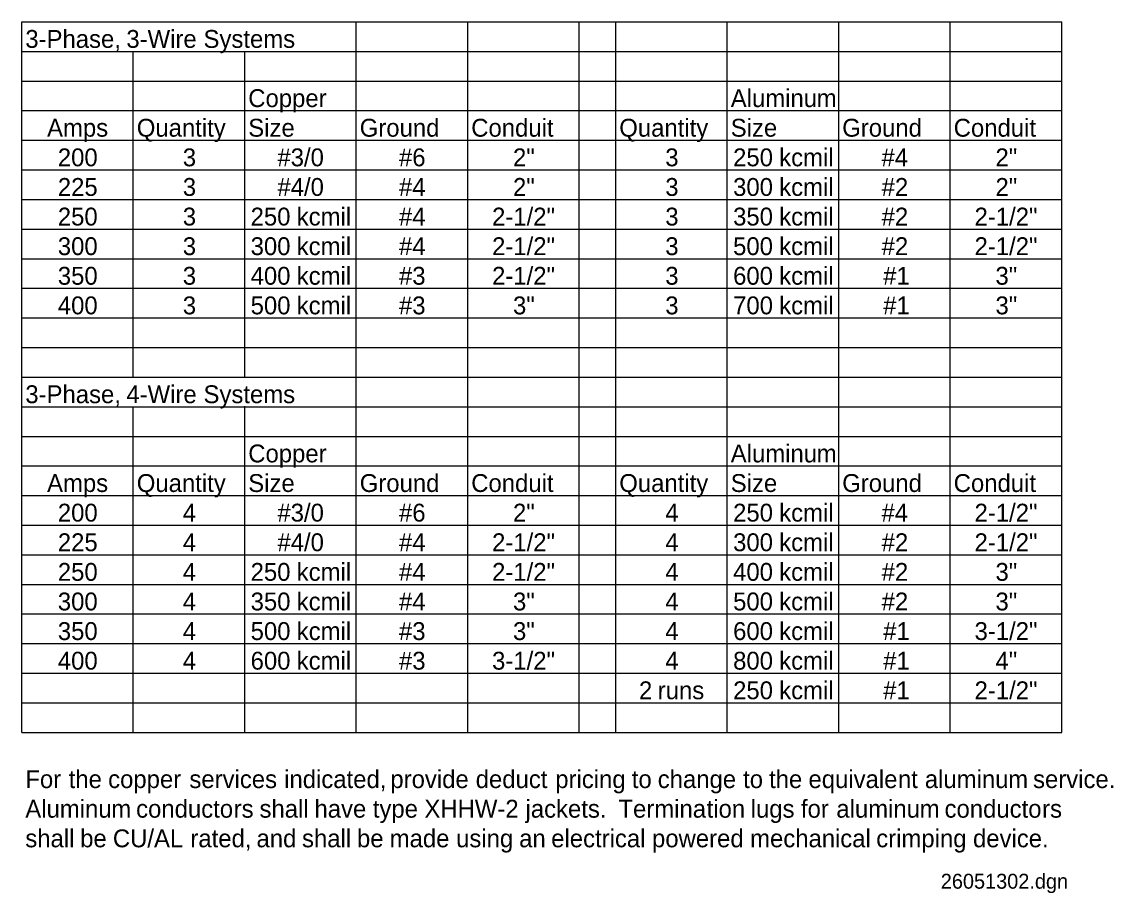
# Model space of a CAD drawing. Extents: x 10073 to 10121.9, y 10117.2 to 10156.2.
import ezdxf

# ---------------------------------------------------------------- set-up
doc = ezdxf.new("R2010")
doc.units = 0
doc.layers.add('Default', color=7, linetype='Continuous')
doc.layers.add('G-ANNO-TEXT', color=7, linetype='Continuous')

msp = doc.modelspace()

# ---------------------------------------------------------------- linework, layer by layer
at = {"layer": 'Default'}
for p, q in [((10073.002, 10124.356), (10073.002, 10156.18)), ((10073.002, 10156.18), (10119.568, 10156.18)), ((10087.978, 10124.356), (10087.978, 10156.18)), ((10092.97, 10124.356), (10092.97, 10156.18)), ((10097.962, 10124.356), (10097.962, 10156.18)), ((10099.6, 10124.356), (10099.6, 10156.18)), ((10104.592, 10124.356), (10104.592, 10156.18)), ((10109.584, 10124.356), (10109.584, 10156.18)), ((10114.576, 10124.356), (10114.576, 10156.18)), ((10119.568, 10124.356), (10119.568, 10156.18)), ((10073.002, 10154.854), (10119.568, 10154.854)), ((10077.994, 10140.268), (10077.994, 10154.854)), ((10082.986, 10140.268), (10082.986, 10154.854)), ((10073.002, 10153.528), (10119.568, 10153.528)), ((10073.002, 10152.202), (10119.568, 10152.202)), ((10073.002, 10150.876), (10119.568, 10150.876)), ((10073.002, 10149.55), (10119.568, 10149.55)), ((10073.002, 10148.224), (10119.568, 10148.224)), ((10073.002, 10146.898), (10119.568, 10146.898)), ((10073.002, 10145.572), (10119.568, 10145.572)), ((10073.002, 10144.246), (10119.568, 10144.246)), ((10073.002, 10142.92), (10119.568, 10142.92)), ((10073.002, 10141.594), (10119.568, 10141.594)), ((10073.002, 10140.268), (10119.568, 10140.268)), ((10073.002, 10138.942), (10119.568, 10138.942)), ((10077.994, 10124.356), (10077.994, 10138.942)), ((10082.986, 10124.356), (10082.986, 10138.974)), ((10073.002, 10137.616), (10119.568, 10137.616)), ((10073.002, 10136.29), (10119.568, 10136.29)), ((10073.002, 10134.964), (10119.568, 10134.964)), ((10073.002, 10133.638), (10119.568, 10133.638)), ((10073.002, 10132.312), (10119.568, 10132.312)), ((10073.002, 10130.986), (10119.568, 10130.986)), ((10073.002, 10129.66), (10119.568, 10129.66)), ((10073.002, 10128.334), (10119.568, 10128.334)), ((10073.002, 10127.008), (10119.568, 10127.008)), ((10073.002, 10125.682), (10119.568, 10125.682)), ((10073.002, 10124.356), (10119.568, 10124.356))]:
    msp.add_line(p, q, dxfattribs=at)
at = {"layer": 'G-ANNO-TEXT'}
msp.add_line((10073.002, 10156.18), (10073.002, 10156.18), dxfattribs=at)

# ---------------------------------------------------------------- texts
at = {"layer": 'Default'}
msp.add_text('26051302.dgn', height=0.66667, dxfattribs=at).set_placement((10114.154, 10117.358))
at = {"layer": 'G-ANNO-TEXT'}
for s, p in [('3-Phase,', (10073.158, 10155.014)), (' 3-Wire', (10077.386, 10155.014)), (' Systems', (10080.842, 10155.014)), ('Copper', (10083.142, 10152.362)), ('Aluminu', (10104.748, 10152.362)), ('m', (10108.598, 10152.362)), ('Amps', (10074.132, 10151.036)), ('Quantity', (10078.15, 10151.036)), ('Size', (10083.142, 10151.036)), ('Ground', (10088.134, 10151.036)), ('Conduit', (10093.126, 10151.036)), ('Quantity', (10099.756, 10151.036)), ('Size', (10104.748, 10151.036)), ('Ground', (10109.74, 10151.036)), ('Conduit', (10114.732, 10151.036)), ('200', (10074.614, 10149.71)), ('3', (10080.211, 10149.71)), ('#3/0', (10084.447, 10149.71)), ('#6', (10089.892, 10149.71)), ('2"', (10094.998, 10149.71)), ('3', (10101.817, 10149.71)), ('250', (10104.854, 10149.71)), (' kcmil', (10106.621, 10149.71)), ('#4', (10111.498, 10149.71)), ('2"', (10116.604, 10149.71)), ('225', (10074.614, 10148.384)), ('3', (10080.211, 10148.384)), ('#4/0', (10084.447, 10148.384)), ('#4', (10089.892, 10148.384)), ('2"', (10094.998, 10148.384)), ('3', (10101.817, 10148.384)), ('300', (10104.854, 10148.384)), (' kcmil', (10106.621, 10148.384)), ('#2', (10111.506, 10148.384)), ('2"', (10116.604, 10148.384)), ('250', (10074.614, 10147.058)), ('3', (10080.211, 10147.058)), ('250', (10083.248, 10147.058)), (' kcmil', (10085.015, 10147.058)), ('#4', (10089.892, 10147.058)), ('2-1/2"', (10094.061, 10147.058)), ('3', (10101.817, 10147.058)), ('350', (10104.854, 10147.058)), (' kcmil', (10106.621, 10147.058)), ('#2', (10111.506, 10147.058)), ('2-1/2"', (10115.667, 10147.058)), ('300', (10074.614, 10145.732)), ('3', (10080.211, 10145.732)), ('300', (10083.248, 10145.732)), (' kcmil', (10085.015, 10145.732)), ('#4', (10089.892, 10145.732)), ('2-1/2"', (10094.061, 10145.732)), ('3', (10101.817, 10145.732)), ('500', (10104.854, 10145.732)), (' kcmil', (10106.621, 10145.732)), ('#2', (10111.506, 10145.732)), ('2-1/2"', (10115.667, 10145.732)), ('350', (10074.614, 10144.406)), ('3', (10080.211, 10144.406)), ('400', (10083.248, 10144.406)), (' kcmil', (10085.015, 10144.406)), ('#3', (10089.892, 10144.406)), ('2-1/2"', (10094.061, 10144.406)), ('3', (10101.817, 10144.406)), ('600', (10104.854, 10144.406)), (' kcmil', (10106.621, 10144.406)), ('#1', (10111.574, 10144.406)), ('3"', (10116.604, 10144.406)), ('400', (10074.614, 10143.08)), ('3', (10080.211, 10143.08)), ('500', (10083.248, 10143.08)), (' kcmil', (10085.015, 10143.08)), ('#3', (10089.892, 10143.08)), ('3"', (10094.998, 10143.08)), ('3', (10101.817, 10143.08)), ('700', (10104.854, 10143.08)), (' kcmil', (10106.621, 10143.08)), ('#1', (10111.574, 10143.08)), ('3"', (10116.604, 10143.08)), ('3-Phase,', (10073.158, 10139.102)), (' 4-Wire', (10077.386, 10139.102)), (' Systems', (10080.842, 10139.102)), ('Copper', (10083.142, 10136.45)), ('Aluminu', (10104.748, 10136.45)), ('m', (10108.598, 10136.45)), ('Amps', (10074.132, 10135.124)), ('Quantity', (10078.15, 10135.124)), ('Size', (10083.142, 10135.124)), ('Ground', (10088.134, 10135.124)), ('Conduit', (10093.126, 10135.124)), ('Quantity', (10099.756, 10135.124)), ('Size', (10104.748, 10135.124)), ('Ground', (10109.74, 10135.124)), ('Conduit', (10114.732, 10135.124)), ('#3/0', (10084.447, 10133.798)), (' kcmil', (10106.621, 10133.798)), ('2-1/2"', (10115.667, 10133.798)), ('200', (10074.614, 10133.798)), ('4', (10080.211, 10133.798)), ('#6', (10089.892, 10133.798)), ('2"', (10094.998, 10133.798)), ('4', (10101.817, 10133.798)), ('250', (10104.854, 10133.798)), ('#4', (10111.498, 10133.798)), ('225', (10074.614, 10132.472)), ('4', (10080.211, 10132.472)), ('#4/0', (10084.447, 10132.472)), ('#4', (10089.892, 10132.472)), ('2-1/2"', (10094.061, 10132.472)), ('4', (10101.817, 10132.472)), ('300', (10104.854, 10132.472)), (' kcmil', (10106.621, 10132.472)), ('#2', (10111.506, 10132.472)), ('2-1/2"', (10115.667, 10132.472)), ('250', (10074.614, 10131.146)), ('4', (10080.211, 10131.146)), ('250', (10083.248, 10131.146)), (' kcmil', (10085.015, 10131.146)), ('#4', (10089.892, 10131.146)), ('2-1/2"', (10094.061, 10131.146)), ('4', (10101.817, 10131.146)), ('400', (10104.854, 10131.146)), (' kcmil', (10106.621, 10131.146)), ('#2', (10111.506, 10131.146)), ('3"', (10116.604, 10131.146)), ('300', (10074.614, 10129.82)), ('4', (10080.211, 10129.82)), ('350', (10083.248, 10129.82)), (' kcmil', (10085.015, 10129.82)), ('#4', (10089.892, 10129.82)), ('3"', (10094.998, 10129.82)), ('4', (10101.817, 10129.82)), ('500', (10104.854, 10129.82)), (' kcmil', (10106.621, 10129.82)), ('#2', (10111.506, 10129.82)), ('3"', (10116.604, 10129.82)), ('350', (10074.614, 10128.494)), ('4', (10080.211, 10128.494)), ('500', (10083.248, 10128.494)), (' kcmil', (10085.015, 10128.494)), ('#3', (10089.892, 10128.494)), ('3"', (10094.998, 10128.494)), ('4', (10101.817, 10128.494)), ('600', (10104.854, 10128.494)), (' kcmil', (10106.621, 10128.494)), ('#1', (10111.574, 10128.494)), ('3-1/2"', (10115.667, 10128.494)), ('400', (10074.614, 10127.168)), ('4', (10080.211, 10127.168)), ('600', (10083.248, 10127.168)), (' kcmil', (10085.015, 10127.168)), ('#3', (10089.892, 10127.168)), ('3-1/2"', (10094.061, 10127.168)), ('4', (10101.817, 10127.168)), ('800', (10104.854, 10127.168)), (' kcmil', (10106.621, 10127.168)), ('#1', (10111.574, 10127.168)), ('4"', (10116.604, 10127.168)), ('2', (10100.639, 10125.842)), (' runs', (10101.182, 10125.842)), ('250', (10104.854, 10125.842)), (' kcmil', (10106.621, 10125.842)), ('#1', (10111.574, 10125.842)), ('2-1/2"', (10115.667, 10125.842)), ('For', (10073.158, 10121.864)), (' the', (10074.803, 10121.864)), (' copper', (10076.57, 10121.864)), (' services', (10080.21, 10121.864)), (' indicated', (10084.452, 10121.864)), (' provide', (10089.209, 10121.864)), (' deduct', (10093.029, 10121.864)), (' pricing', (10096.593, 10121.864)), (' to', (10100.02, 10121.864)), (' change', (10101.182, 10121.864)), (' to', (10105.004, 10121.864)), (' the', (10106.166, 10121.864)), (' equivale', (10107.932, 10121.864)), ('nt', (10112.236, 10121.864)), (' aluminu', (10113.142, 10121.864)), ('m', (10117.174, 10121.864)), (' service.', (10117.989, 10121.864)), (',', (10089.028, 10121.864)), ('Aluminu', (10073.158, 10120.538)), ('m', (10077.008, 10120.538)), (' conducto', (10077.823, 10120.538)), ('rs', (10082.489, 10120.538)), (' shall', (10083.349, 10120.538)), (' have', (10085.81, 10120.538)), (' type', (10088.423, 10120.538)), (' XHHW-2', (10090.733, 10120.538)), (' jackets.', (10095.26, 10120.538)), ('  Termina', (10099.125, 10120.538)), ('tion', (10103.668, 10120.538)), (' lugs', (10105.344, 10120.538)), (' for', (10107.594, 10120.538)), (' aluminu', (10109.179, 10120.538)), ('m', (10113.211, 10120.538)), (' conducto', (10114.026, 10120.538)), ('rs', (10118.692, 10120.538)), ('shall', (10073.158, 10119.212)), (' be', (10075.317, 10119.212)), (' CU/AL', (10076.782, 10119.212)), (' rated,', (10080.254, 10119.212)), (' and', (10083.213, 10119.212)), (' shall', (10085.252, 10119.212)), (' be', (10087.714, 10119.212)), (' made', (10089.178, 10119.212)), (' using', (10092.153, 10119.212)), (' electrical', (10096.411, 10119.212)), (' powered', (10100.925, 10119.212)), (' mechani', (10105.319, 10119.212)), ('cal', (10109.653, 10119.212)), (' crimping', (10110.967, 10119.212)), (' device.', (10115.299, 10119.212)), (' an', (10094.976, 10119.212))]:
    msp.add_text(s, height=0.8, dxfattribs=at).set_placement(p)

doc.saveas('drawing.dxf')
